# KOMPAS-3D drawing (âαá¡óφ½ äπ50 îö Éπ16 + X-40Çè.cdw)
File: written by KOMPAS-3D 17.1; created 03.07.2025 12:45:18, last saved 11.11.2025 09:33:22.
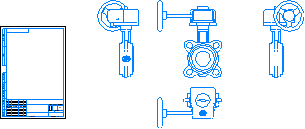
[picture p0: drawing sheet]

Sheet 1: A4, portrait

Title block, sheet 1: sheets: 1; sheet format: A4; stored path: \\adlc.lan\data\АДЛ_ПКД\3D-модели\ADL production\Дисковые поворотные затворы ГРАНВЭЛ\межфланцевый с китайским редуктором Ру16\KOMPAS 2D\Гранвэл Ду50 МФ Ру16 + X-40АК.cdw

Views: Вид 1, Спереди, Проекционный вид 2, Проекционный вид 3, Проекционный вид 4
Referenced files in \\adlc.lan\data\АДЛ_ПКД\3D-модели\ADL production\Дисковые поворотные затворы ГРАНВЭЛ\межфланцевый с китайским редуктором Ру16\KOMPAS 3D\: Гранвэл Ду50 МФ Ру16 + X-40АК.m3d
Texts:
  Andrey
  АДЛ
Dimensions and other numbers on the sheet: 1:1; 1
